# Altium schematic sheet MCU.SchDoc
size A4; SheetNumber: 2; SheetTotal: 2
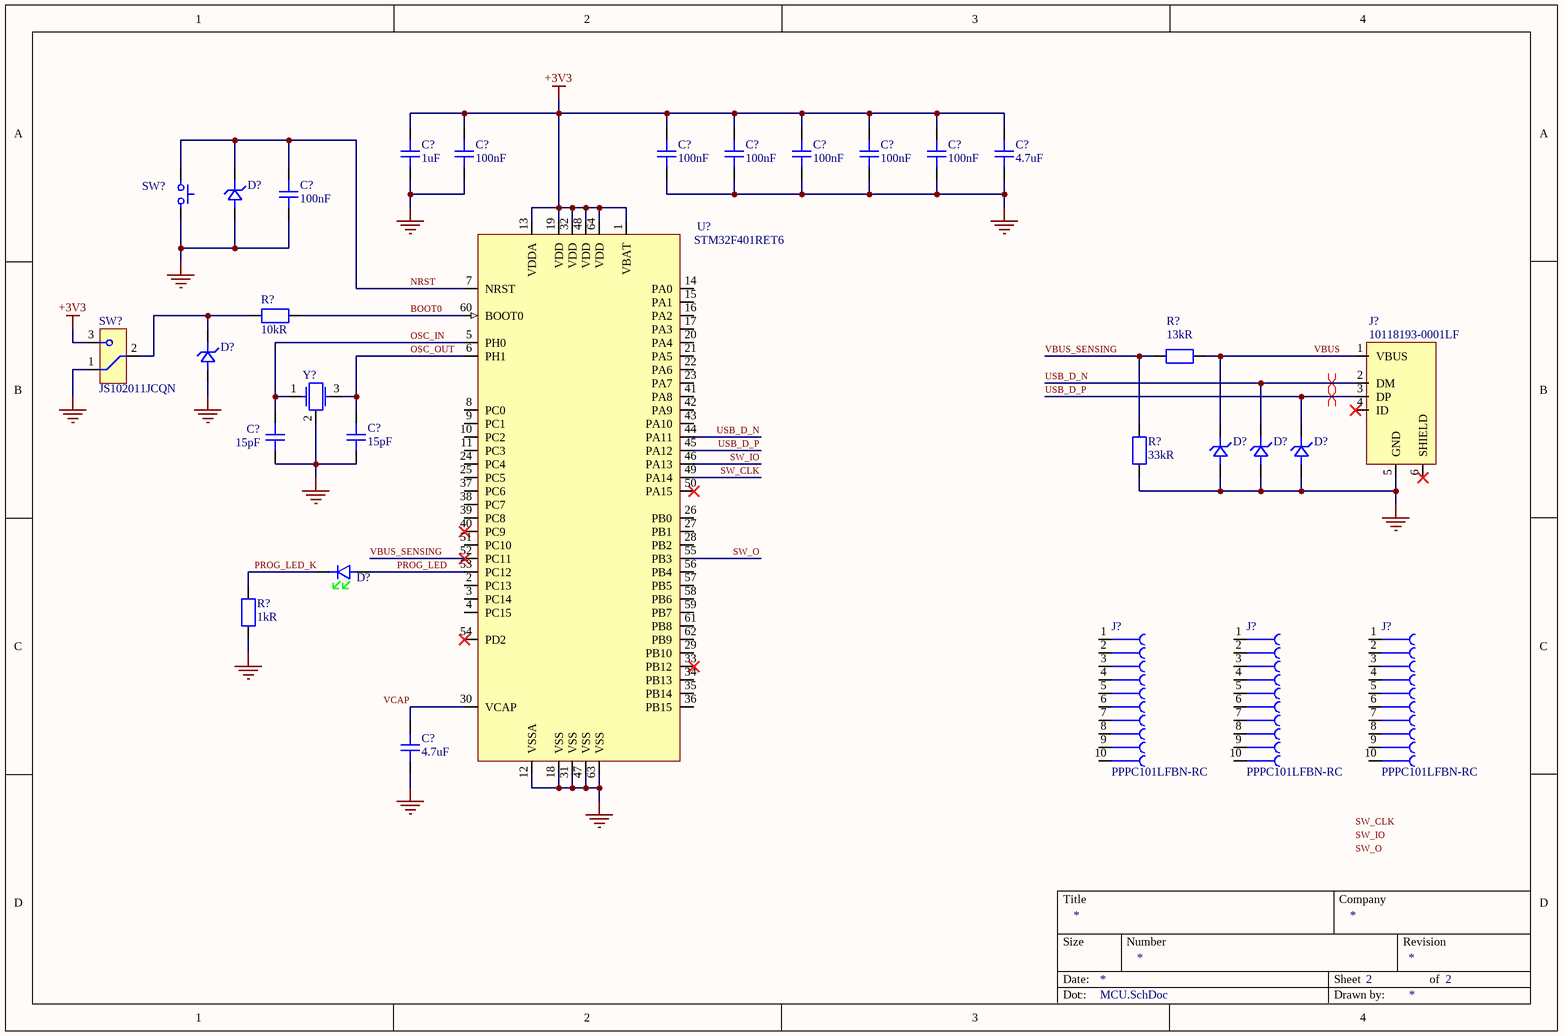
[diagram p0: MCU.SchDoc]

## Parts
(Parts that share a designator on the sheet are numbered #1, #2 ... from top to bottom, then left to right.)
C?#1  value 1uF  [C_Yageo_CC_0402_A]  (hidden comment: CC0402MRX5R6BB105)
C?#2  value 100nF  [C_Yageo_CC_0402_A]  (hidden comment: CC0402MRX5R6BB104)
C?#3  value 100nF  [C_Yageo_CC_0402_A]  (hidden comment: CC0402MRX5R6BB104)
C?#4  value 100nF  [C_Yageo_CC_0402_A]  (hidden comment: CC0402MRX5R6BB104)
C?#5  value 100nF  [C_Yageo_CC_0402_A]  (hidden comment: CC0402MRX5R6BB104)
C?#6  value 100nF  [C_Yageo_CC_0402_A]  (hidden comment: CC0402MRX5R6BB104)
C?#7  value 100nF  [C_Yageo_CC_0402_A]  (hidden comment: CC0402MRX5R6BB104)
C?#8  value 4.7uF  [C_Yageo_CC_0402_A]  (hidden comment: CC0402MRX5R6BB475)
C?#9  value 100nF  [C_Yageo_CC_0402_A]  (hidden comment: CC0402MRX5R6BB104)
C?#10  value 15pF  [C_Yageo_CC_0402_A]  (hidden comment: CC0402JRNPO9BN150)
C?#11  value 15pF  [C_Yageo_CC_0402_A]  (hidden comment: CC0402JRNPO9BN150)
C?#12  value 4.7uF  [C_Yageo_CC_0402_A]  (hidden comment: CC0402MRX5R6BB475)
D?#1  D5V0F1U2S9-7  [D_TVS_Uni_Diodes_SOD-923_B]  (value not drawn)
D?#2  D5V0F1U2S9-7  [D_TVS_Uni_Diodes_SOD-923_B]  (value not drawn)
D?#3  D5V0F1U2S9-7  [D_TVS_Uni_Diodes_SOD-923_B]  (value not drawn)
D?#4  D5V0F1U2S9-7  [D_TVS_Uni_Diodes_SOD-923_B]  (value not drawn)
D?#5  D5V0F1U2S9-7  [D_TVS_Uni_Diodes_SOD-923_B]  (value not drawn)
D?#6  150080GS75000  [D_LED_We_150080GS75000]  (value not drawn)
J?#1  10118193-0001LF  [J_USB_Micro-B_Amphenol_10118193-0001LF]
J?#2  PPPC101LFBN-RC  [J_Sullins_PPPC101LFBN-RC]
J?#3  PPPC101LFBN-RC  [J_Sullins_PPPC101LFBN-RC]
J?#4  PPPC101LFBN-RC  [J_Sullins_PPPC101LFBN-RC]
R?#1  value 10kR  [R_Yageo_RCL_0402_A]  (hidden comment: RC0402FR-0710KL)
R?#2  value 13kR  [R_Yageo_RCL_0402_A]  (hidden comment: RC0402FR-0713KL)
R?#3  value 33kR  [R_Yageo_RCL_0402_A]  (hidden comment: RC0402FR-0733KL)
R?#4  value 1kR  [R_Yageo_RCL_0402_A]  (hidden comment: RC0402FR-071KL)
SW?#1  PTS647SN50SMTR2LFS  [SW_Tactitle_SPST_C&K_PTS647SN50SMTR2LFS]  (value not drawn)
SW?#2  JS102011JCQN  [SW_Slide_C&K_JS102011JCQN]
U?  STM32F401RET6  [U_STM32F401xD/xE_B]
Y?  ECS-240-12-37B-CKY-TR  [Y_Crystal_GND24_ECS_240-12-37B-CKY-TR]  (value not drawn)

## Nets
+3V3: C?#1.2 C?#2.2 C?#3.2 C?#4.2 C?#5.2 C?#6.2 C?#7.2 C?#8.2 SW?#2.3 U?.1(VBAT) U?.13(VDDA) U?.19(VDD) U?.32(VDD) U?.48(VDD) U?.64(VDD)
GND: C?#1.1 C?#2.1 C?#3.1 C?#4.1 C?#5.1 C?#6.1 C?#7.1 C?#8.1 C?#9.1 C?#10.1 C?#11.1 C?#12.1 D?#1.2 D?#2.2 D?#3.2 D?#4.2 D?#5.2 J?#1.5(GND) R?#3.1 R?#4.1 SW?#1.2 SW?#2.1 U?.12(VSSA) U?.18(VSS) U?.31(VSS) U?.47(VSS) U?.63(VSS) Y?.2
BOOT0: R?#1.2 U?.60(BOOT0)
NRST: C?#9.2 D?#1.1 SW?#1.1 U?.7(NRST)
OSC_IN: C?#10.2 U?.5(PH0) Y?.1
OSC_OUT: C?#11.2 U?.6(PH1) Y?.3
PROG_LED: D?#6.1 U?.53(PC12)
PROG_LED_K: D?#6.2 R?#4.2
SW_CLK: U?.49(PA14)
SW_IO: U?.46(PA13)
SW_O: U?.55(PB3)
USB_D_N: D?#4.1 J?#1.2(DM) U?.44(PA11)
USB_D_P: D?#5.1 J?#1.3(DP) U?.45(PA12)
VBUS: D?#3.1 J?#1.1(VBUS) R?#2.2
VBUS_SENSING: R?#2.1 R?#3.2 U?.52(PC11)
NetC?#12_2: C?#12.2 U?.30(VCAP)
NetD?#2_1: D?#2.1 R?#1.1 SW?#2.2

Not connected (* = marked no-connect by the designer): J?#1 4(ID)* 6(SHIELD)*; J?#2 1 2 3 4 5 6 7 8 9 10; J?#3 1 2 3 4 5 6 7 8 9 10; J?#4 1 2 3 4 5 6 7 8 9 10; U? 2(PC13) 3(PC14) 4(PC15) 8(PC0) 9(PC1) 10(PC2) 11(PC3) 14(PA0) 15(PA1) 16(PA2) 17(PA3) 20(PA4) 21(PA5) 22(PA6) 23(PA7) 24(PC4) 25(PC5) 26(PB0) 27(PB1) 28(PB2) 29(PB10) 33(PB12)* 34(PB13) 35(PB14) 36(PB15) 37(PC6) 38(PC7) 39(PC8) 40(PC9)* 41(PA8) 42(PA9) 43(PA10) 50(PA15)* 51(PC10) 54(PD2)* 56(PB4) 57(PB5) 58(PB6) 59(PB7) 61(PB8) 62(PB9)

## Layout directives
differential pair; differential pair class USB: USB_D_N, USB_D_P

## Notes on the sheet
- Labels drawn without touching a wire or pin: SW_CLK, SW_IO, SW_O, VCAP

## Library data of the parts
C?#1 = CMP-001-00016-7: Multilayer Ceramic Capacitor, 1 uF, 50 V, ± 10%, X5R, 0402 [1005 Metric]; Voltage Rating (DC): 10V; Tolerance: 20%; Temperature Coefficient: 30ppm/°C
C?#2-C?#7 C?#9 = CMP-001-00009-8: Multilayer Ceramic Capacitor, 0.1 uF, 25 V, ± 20%, X7R, 0402 [1005 Metric]; Dielectric: X5R; Temperature Coefficient: 30ppm/°C; Voltage Rating: 10V
C?#8 C?#12 = CMP-001-00015-8: Multilayer Ceramic Capacitor, 4.7 uF, 50 V, ± 10%, X5R, 0402 [1005 Metric]; Tolerance: 20%; Temperature Coefficient: 30ppm/°C; Voltage Rating (DC): 10V
C?#10 C?#11 = CMP-001-00017-9: Multilayer Ceramic Capacitor, 15 pF, 10 V, ± 5%, X7R, 0402 [1005 Metric]; Insulation Resistance: 100GR; Dielectric: C0G; Voltage Rating (DC): 50V; Temperature Coefficient: 30ppm/°C
D?#1-D?#5 = CMP-004-00003-1: Diode TVS Dual Uni-Dir 5.5V 250000W 2-Pin SOD-923 T/R; Max Power Dissipation: 250mW; ESD Protection: Yes; Max Reverse Leakage Current: 100nA; Capacitance: 0.5pF @ 1MHz; Max Surge Current: 1.5A; Diode Type: ZENER; Direction: Unidirectional; Breakdown Voltage: 6V; Clamping Voltage: 10V; Value: 5E-13F; Peak Pulse Power: 250kW; Number of Unidirectional Channels: 1
D?#6 = CMP-007-00000-6: WURTH ELEKTRONIK - 150080GS75000 - LED, Green, SMD, 0805, 30 mA, 3.2 V, 520 nm; Viewing Angle: 140°; Lens Transparency: Clear; Reverse Voltage: 5V; Lens Size: 1.25mm; Lens Color: Colorless; Lens Style: Clear,Flat,Rectangular; Power Dissipation: 105mW; Wavelength: 520nm; Forward Voltage: 3.2V; Test Current: 20mA; Forward Current: 30mA; Luminous Intensity: 450mcd
J?#1 = CMP-002-00002-7: Usb Connector, 5 Contact(S), Female, Right Angle, Surface Mount Terminal, Locking, Receptacle; Number of Contacts: 5; Current Rating: 1.8A; Connector Type: USB,Receptacle; Pitch: 650um; Number of Ports: 1; Voltage Rating: 100V; USB Standard: USB 2.0; Insulation Resistance: 1GR
J?#2-J?#4 = CMP-002-00003-1: 10 Position Total Single Row 2.54 mm Pitch Straight Female Header; Voltage Rating: 250V; Number of Contacts: 10; Pitch: 0.1inch; Current Rating: 3A
R?#1 = CMP-009-00003-7: SMD Chip Resistor, 10 kOhm, ± 1%, 62.5 mW, 0402 [1005 Metric], Thick Film, General Purpose; Power Rating: 62.5mW; Max Power Dissipation: 63mW; Temperature Coefficient: 100ppm/°C; Voltage Rating (DC): 50V
R?#2 = CMP-009-00001-7: SMD Chip Resistor, 13 kOhm, ± 1%, 63 mW, 0402 [1005 Metric], Thick Film, General Purpose; Voltage Rating (DC): 50V; Temperature Coefficient: 100ppm/°C; Max Power Dissipation: 63mW; Power Rating: 62.5mW
R?#3 = CMP-009-00005-8: SMD Chip Resistor, 33 kOhm, ± 1%, 63 mW, 0402 [1005 Metric], Thick Film, General Purpose; Power Rating: 63mW; Temperature Coefficient: 100ppm/°C; Voltage Rating (AC): 50V
R?#4 = CMP-009-00002-7: SMD Chip Resistor, 1 kOhm, ± 1%, 62.5 mW, 0402 [1005 Metric], Thick Film, General Purpose; Temperature Coefficient: 100ppm/°C; Max Power Dissipation: 63mW; Voltage Rating (AC): 50V; Power Rating: 62.5mW
SW?#1 = CMP-011-00000-10: Switch Tactile N.O. SPST Round Button Gull Wing 0.05A 12VDC 100000Cycles 0.98N SMD T/R; pin to pad: 1>1+2 2>3+4; Ratings: IP40; Switch Function: Off-Mom; Illumination Type: Non-Illuminated; Actuator Type: Standard; Number of Positions: 2; Operating Force: 100gf; Switch Travel: 0.25mm
SW?#2 = CMP-011-00001-7: JS Series Sub-Miniature Slide Switch SPDT On-On Top Slide 0.3A 6VDC J-Lead Surface Mount T/R; Voltage Rating (DC): 6V; Switch Travel: 2mm; Actuator Material: Nylon,Polyamide,PA46; Electrical Life: 5000Cycles; Actuator Type: Standard
U? = CMP-020-00000-6: MCU 32-bit STM32 ARM Cortex M4 RISC 512KB Flash 1.8V/2.5V/3.3V 64-Pin LQFP Tray; Operating Supply Voltage: 3.3V; Peripherals: Brown-out Detect/Reset,POR,PWM,WDT,DMA; Nominal Supply Current: 1.8uA; Number of ADC Channels: 12; Interface: I2C,SPI,USB,IrDA,SDIO,UART,USART,LIN,I2S; Clock Frequency: 84MHz; Number of USB Channels: 1; Number of Timers/Counters: 8; Number of Channels: 16; Number of PWM Channels: 23; Number of UART Channels: 3; Number of Programmable I/O: 50; Watchdog Timer: Yes; Max Power Dissipation: 313mW; Min Supply Voltage: 1.7V; Data Bus Width: 32b; RAM Size: 96KB; Max Supply Voltage: 3.6V; Oscillator Type: Internal
Y? = CMP-003-00000-4: Crystal 24MHz ±10ppm (Tol) ±10ppm (Stability) 12pF FUND 50Ohm 4-Pin Mini-CSMD T/R; pin to pad: 2>2+4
